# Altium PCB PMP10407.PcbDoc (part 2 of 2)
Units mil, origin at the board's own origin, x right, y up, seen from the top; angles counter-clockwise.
Board outline 4400 x 1900 mil, 4 copper layers (Top Layer, Signal Layer 1, Signal Layer 2, Bottom Layer), stack 60.6 mil thick; 66 components, 38 nets, 182 pads, 41 vias.
Unrouted connection lines stored in the file: 1.
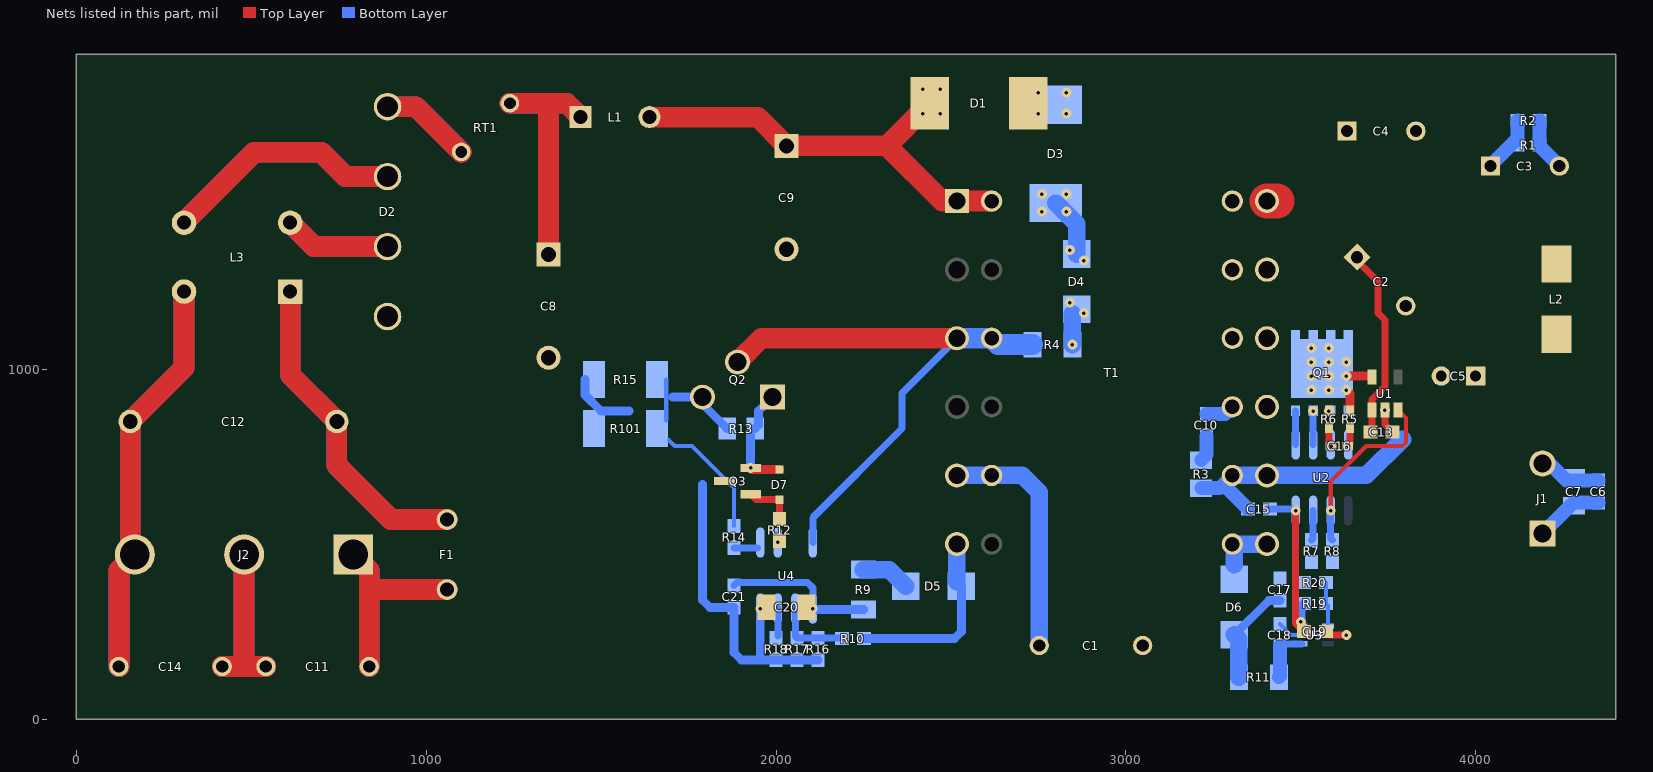
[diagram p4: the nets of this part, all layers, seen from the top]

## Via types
v1: diameter 28, hole 10, Top Layer to Bottom Layer, 41 vias

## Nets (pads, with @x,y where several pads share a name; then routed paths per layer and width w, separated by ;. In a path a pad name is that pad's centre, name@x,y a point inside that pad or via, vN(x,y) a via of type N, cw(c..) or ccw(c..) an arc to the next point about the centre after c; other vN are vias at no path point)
5VDD: C15.1 C19.1 R19.1 U2.4 U3.5 | length 480.4
  Top Layer w20: v1@3485,589.01 3485,273.51 C19.1@3508.51,250
  Bottom Layer w20: C15.1@3411.5,600 3480.51,600 v1(3485,595.51)
  Bottom Layer w25: v1(3500,277.26) 3500,321.49 R19.1@3508.51,330
EN: R8.2 U1.3 U2.2 | length 532.4
  Top Layer w12: v1(3585,595.51) 3585,678.54 3686.46,780 3790,780 3800,790 3800,860.16 U1.3@3777.4,882.76
  Bottom Layer w20: v1(3585,595.51) 3585,516.5 R8.2@3590,511.5
GND: C1.2 C8.2 C9.2 C20.2 C21.2 D2.4 Q3.3 R15.1 R16.1 R17.1 R18.1 R101.1 T1.5 T1.8 U4.4 | length 1829
  Bottom Layer w25: R15.1@1453.86,970 1453.86,926.14 1500,880 1580,880 ; 1790,670 1790,340 1811.5,318.5 C21.2@1880,318.5 1880,190 1901.5,168.5 R18.1@2000,168.5 R17.1@2060,168.5 R16.1@2120,168.5 ; 1955,175 v1(1955,315.51)
  Bottom Layer w50: T1.5@2517,696 T1.8@2616,696 2704,696 2752.36,647.64 C1.2@2752.36,210
GND2: C1.1 C2.2 C3.2 C4.2 C5.2 C6.2 C7.2 C11.2 C13.2 C14.1 C15.2 C17.2 C18.2 C19.2 J1.2 J2.2 Q1.1 Q1.2 Q1.3 R1.1 R2.1 R3.2 R6.2 R7.1 R8.1 R20.1 T1.17 T1.20 U1.2 U2.6 U3.2 | length 2369.5
  Top Layer w20: C19.2@3571.5,250 3581.5,240 v1(3630,240) ; v1(3740,882.76) 3740,841.5 C13.2@3761.5,820
  Top Layer w59.06: C14.1@417.64,150 480,150 ; J2.2@480,470 480,150 ; C11.2@542.36,150 480,150
  Bottom Layer w12: C18.2@3440,271.49 3471.5,240 U3.2@3577.41,240 v1(3630,240)
  Bottom Layer w20: Q1.3@3534.84,880.7 3534.84,784.65 U2.6@3535,784.49
  Bottom Layer w39.37: R3.2@3215,660 3268,660 T1.17@3304,696 ; 3288.5,660 C15.2@3348.5,600 ; R2.1@4181.5,1710 R1.1@4181.5,1640 4181.5,1636.93 C3.2@4238.43,1580 ; J1.2@4200,740 4258.5,681.5 C6.2@4350,681.5
  Bottom Layer w50: T1.17@3304,696 T1.20@3403,696 3686.79,696 3790.79,800
  Bottom Layer w59.06: C14.1@417.64,150 480,150 ; J2.2@480,470 480,150 ; C11.2@542.36,150 480,150
  other v1: 3534.84,880 3580,880
NetC2_1: C2.1 C3.1 C4.1 C13.1 L2.1 R1.2 R2.2 T1.13 T1.14 T1.23 T1.24 U1.1 | length 700.9
  Top Layer w20: 3680,1290 3720,1250 3720,1160 3740,1140 3740,950.16 3702.6,912.76 U1.1@3702.6,882.76 3702.6,824.09 C13.1@3698.5,820
  Top Layer w100: T1.24@3403,1480 T1.24@3431.57,1480
  Bottom Layer w39.37: C3.1@4041.57,1581.57 4118.5,1658.5 R2.2@4118.5,1710
NetC5_1: C5.1 C6.1 C7.1 J1.1 L2.2 | length 182.5
  Bottom Layer w39.37: J1.1@4200,540 4278.5,618.5 C6.1@4350,618.5
NetC8_1: C8.1 L1.1 RT1.1 | length 1290.7
  Top Layer w59.06: RT1.1@1239.6,1759.6 1401.98,1759.6 L1.1@1441.57,1720 ; C8.1@1350,1327.64 1350,1749.6
  Bottom Layer w59.06: RT1.1@1239.6,1759.6 1350,1759.6 ; C8.1@1350,1327.64 1350,1759.6 ; L1.1@1441.57,1720 1401.98,1759.6 1350,1759.6
NetC9_1: C9.1 D1.2 L1.2 T1.1 T1.12 | length 1250
  Top Layer w59.06: L1.2@1638.43,1720 1947.64,1720 C9.1@2030,1637.64 2317.15,1637.64 ; D1.2@2439.51,1760 2317.15,1637.64 ; T1.12@2616,1480 T1.1@2517,1480 2474.78,1480 2317.15,1637.64
  other v1: 2420,1730 2470,1730 2420,1800 2470,1800
NetC10_1: C10.1 R3.1 | length 74.7
  Bottom Layer w39.37: R3.1@3215,740 3230,755 C10.1@3230,808.5
NetC10_2: C10.2 Q1.5 Q1.6 Q1.7 Q1.8 Q1.9 R5.2 T1.15 T1.16 T1.21 T1.22 U1.5 | length 220.6
  Top Layer w25: v1(3630,940) 3640,930 R5.2@3640,879.76 ; v1(3630,980) 3699.84,980 U1.5@3702.6,977.24
  Bottom Layer w39.37: C10.2@3230,871.5 3283.5,871.5 T1.16@3304,892
  other v1: 3530,940 3580,940 3530,980 3580,980 3530,1020 3580,1020 3630,1020 3530,1060 3580,1060
NetC11_1: C11.1 F1.2 J2.1 | length 1126.7
  Top Layer w59.06: J2.1@792,470 837.64,424.36 837.64,370 ; C11.1@837.64,150 837.64,370 ; F1.2@1060,370 837.64,370
  Bottom Layer w59.06: J2.1@792,470 837.64,424.36 837.64,380 ; C11.1@837.64,150 837.64,380 ; F1.2@1060,370 847.64,370 837.64,380
NetC12_1: C12.1 F1.1 L3.1 | length 1862.1
  Top Layer w59.06: L3.1@611.57,1221.57 611.57,983.7 C12.1@745.28,850 745.28,724.72 900,570 F1.1@1060,570
  Bottom Layer w59.06: L3.1@611.57,1221.57 611.57,983.7 C12.1@745.28,850 745.28,724.72 900,570 F1.1@1060,570
NetC12_2: C12.2 C14.2 J2.3 L3.4 | length 2281.7
  Top Layer w59.06: C14.2@122.36,150 122.36,424.36 J2.3@168,470 ; J2.3@154.72,483.28 C12.2@154.72,850 308.43,1003.7 L3.4@308.43,1221.57
  Bottom Layer w59.06: C14.2@122.36,150 122.36,424.36 J2.3@168,470 ; J2.3@154.72,483.28 C12.2@154.72,850 308.43,1003.7 L3.4@308.43,1221.57
NetC16_1: C16.1 R5.1 U2.8 | length 55.2
  Top Layer w20: v1(3633.62,780) 3640,786.38 R5.1@3640,832.52
NetC16_2: C16.2 R6.1 U2.7 | length 55.2
  Top Layer w20: R6.1@3580,832.52 3580,786.38 v1(3586.38,780)
NetC17_1: C17.1 D6.1 R11.1 | length 296.9
  Bottom Layer w25: D6.1@3310,241.26 3311.26,241.26 3408.5,338.5 C17.1@3440,338.5
  Bottom Layer w50: D6.1@3310,241.26 3322.91,228.35 R11.1@3322.91,120
NetC18_1: C18.1 R11.2 U3.4 | length 154.8
  Bottom Layer w20: C18.1@3440,208.5 3445.91,214.41 U3.4@3502.6,214.41
  Bottom Layer w39.37: R11.2@3437.09,120 3440,122.92 C18.1@3440,208.5
NetC20_1: C20.1 C21.1 R9.1 U4.1 | length 436.6
  Bottom Layer w20: C21.1@1880,381.5 1888.5,390 2090,390 2105,375 v1(2105,315.51)
  Bottom Layer w25: U4.1@2107.6,312.91 R9.1@2250,312.91
NetD1_1: D1.1 D3.2
  other v1: 2750,1730 2830,1730 2750,1790 2830,1790
NetD2_1: D2.1 RT1.2 | length 528.2
  Top Layer w59.06: D2.1@890,1750 970.81,1750 RT1.2@1100.4,1620.4
  Bottom Layer w59.06: D2.1@890,1750 970.81,1750 RT1.2@1100.4,1620.4
NetD2_2: D2.2 L3.3 | length 1388.1
  Top Layer w59.06: L3.3@308.43,1418.43 510,1620 700,1620 770,1550 D2.2@890,1550
  Bottom Layer w59.06: L3.3@308.43,1418.43 510,1620 700,1620 770,1550 D2.2@890,1550
NetD2_3: D2.3 L3.2 | length 613.5
  Top Layer w59.06: L3.2@611.57,1418.43 680,1350 D2.3@890,1350
  Bottom Layer w59.06: L3.2@611.57,1418.43 680,1350 D2.3@890,1350
NetD3_1: D3.1 D4.1 | length 170.6
  Bottom Layer w50: D3.1@2800,1474.51 2860,1414.51 D4.1@2860,1328.74
  other v1: 2880,1310 2840,1340 2760,1450 2830,1450 2760,1500 2830,1500
NetD4_2: D4.2 R4.1 | length 88.3
  Bottom Layer w50: v1(2847.09,1070) D4.2@2847.09,1158.35
  other v1: 2880,1160 2840,1190
NetD5_1: D5.1 R9.2 | length 140.8
  Bottom Layer w50: R9.2@2250,427.09 2324.17,427.09 D5.1@2371.26,380
NetD5_2: D5.2 R10.2 T1.6 | length 525.6
  Bottom Layer w25: R10.2@2251.5,230 2510,230 2530,250 2530,378.74 D5.2@2528.74,380
  Bottom Layer w50: D5.2@2517,391.74 T1.6@2517,500
NetD6_2: D6.2 T1.18 T1.19 | length 160.4
  Bottom Layer w50: 3310,441.11 3310,494 T1.18@3304,500 T1.19@3403,500
NetD7_1: D7.1 Q2.1 Q3.2 R13.2 | length 295
  Top Layer w25: v1(1927.4,717.4) 1931.5,713.31 D7.1@2010,713.31
  Bottom Layer w25: v1(1927.4,717.4) R13.2@1927.4,817.4 ; R13.2@1940,830 1950,840 1950,880 Q2.1@1990,920
NetD7_2: D7.2 Q3.1 R12.1 | length 144.4
  Top Layer w20: Q3.1@1927.4,642.6 1943.31,626.69 D7.2@2010,626.69 R12.1@2010,571.5
NetQ1_4: Q1.4 U2.5 | length 96.4
  Bottom Layer w20: Q1.4@3484.51,880.7 3485,880.2 U2.5@3485,784.49
NetQ2_2: Q2.2 R4.2 T1.3 T1.10 U4.8 | length 1632.7
  Top Layer w59.06: Q2.2@1890,1020 1958,1088 T1.3@2517,1088
  Bottom Layer w20: U4.8@2105,504.49 2105,575 2360,830 2360,931 T1.3@2517,1088
  Bottom Layer w59.06: T1.3@2517,1088 T1.10@2616,1088 2634,1070 R4.2@2732.91,1070
NetQ2_3: Q2.3 R13.1 R14.2 R15.2 R101.2 | length 671
  Bottom Layer w12: R101.2@1686.14,853.86 R15.2@1686.14,970 ; 1694.17,796.38 1710.55,780 1760,780 1880,660 R14.2@1880,551.5
  Bottom Layer w25: 1704.93,920 Q2.3@1790,920 1790,900 R13.1@1860,830
NetR7_2: R7.2 U2.3 | length 86.1
  Bottom Layer w20: R7.2@3530,511.5 3535,516.5 U2.3@3535,595.51
NetR10_1: R10.1 R16.2 R17.2 U4.2 | length 213.1
  Bottom Layer w20: U4.2@2055,315.51 2055,236.5 R17.2@2060,231.5 R16.2@2120,231.5 R10.1@2187.01,231.5
NetR12_2: R12.2 U4.6
  other v1: 2005,504.49
NetR14_1: R14.1 U4.5 | length 66.9
  Bottom Layer w20: R14.1@1880,488.5 U4.5@1946.93,488.5
NetR18_2: R18.2 U4.3 | length 79
  Bottom Layer w20: R18.2@2005,236.5 U4.3@2005,315.51
NetR19_2: R19.2 R20.2 U3.1 | length 126.9
  Bottom Layer w12: R20.2@3571.5,390 R19.2@3571.5,330 3577.41,324.09 U3.1@3577.41,265.59
pads on no net: HS1.0 T1.2 T1.4 T1.7 T1.9 T1.11 U1.4 U2.1 U3.3

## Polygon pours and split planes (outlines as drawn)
NetD4_2 on Top Layer "D4_2" (solid, pour order 74): 2840,1010 2820,1030 2820,1060 2820,1210 2830,1220 2860,1220 2970,1220 2990,1200 2990,1030 2970,1010
NetC5_1 on Top Layer "C5_1" (solid, remove dead copper, pour order 75): 3970,1020 4130,1180 4180,1180 4380,1180 4390,1170 4390,980 4390,460 4380,450 4320,450 3980,450 3970,460
GND2 on Top Layer "GND2" (solid, remove dead copper, pour order 81): 3270,1880 3280,1890 3310,1890 4380,1890 4390,1880 4390,1870 4390,40 4370,20 3040,20 3020,40 3020,80 3020,490 3270,740
NetD3_1 on Top Layer "D3_1" (solid, pour order 73): 2740,1550 2720,1530 2720,1510 2720,1310 2720,1300 2740,1280 2760,1280 2970,1280 2990,1300 2990,1340 2990,1530 2970,1550
NetC10_2 on Top Layer "C10_2" (solid, remove dead copper, pour order 57): 3270,1200 3278.5,1208.5 3450,1208.5 3661.5,1208.5 3670,1200 3670,1180 3670,931.57 3658.43,920 3580,920 3460,920 3440,900 3440,870 3440,860 3430,850 3280,850 3270,860
NetC2_1 on Top Layer "NetC2_1" (solid, remove dead copper, pour order 53): 3270,1520 3270,1260 3280,1250 3290,1250 3640,1250 3710,1320 4080,1320 4090,1320 4170,1240 4250,1240 4280,1240 4290,1250 4290,1270 4290,1350 4100,1540 4100,1600 4090,1610 4040,1610 3770,1610 3670,1710 3620,1710 3590,1710 3410,1530 3280,1530
GND on Top Layer "GND" (solid, pour order 80): 850,1170 870,1190 900,1190 980,1190 1630,1190 1850,1410 2100,1410 2170,1340 2270,1240 2270,890 2400,760 2401.5,761.5 2490,761.5 2758.5,761.5 2780,740 2780,730 2780,40 2760,20 2740,20 1460,20 1440,40 1440,110 1440,570 1190,820 920,1090 870,1090 850,1110
NetD1_1 on Top Layer "D1_1" (solid, pour order 69): 2680,1660 2660,1680 2660,1720 2660,1870 2660.08,1870 2680,1889.92 2680.08,1890 2700,1890 2940,1890 2960,1870 2960,1720 2960,1680 2940,1660
NetC9_1 on Top Layer "C9_1" (solid, pour order 65): 1600,1870 1620,1890 1650,1890 1940,1890 2500,1890 2520,1870 2520,1830 2520,1580 2580,1520 2630,1520 2650,1500 2650,1470 2650,1460 2630,1440 2600,1440 2510,1440 2460,1440 2280,1440 2130,1590 2070,1590 1620,1590 1600,1610
NetC8_1 on Top Layer "C8_1" (solid, pour order 61): 1210,1870 1230,1890 1470,1890 1490,1870 1490,1840 1490,1310 1470,1290 1310,1290 1230,1290 1210,1310
NetD2_1 on Top Layer "D2_1" (solid, pour order 59): 850,1710 830,1730 830,1868.98 850,1888.98 851.02,1890 940,1890 1110,1890 1130,1870 1130,1840 1130,1610 1110,1590 1080,1590 1030,1640 960,1710
GND2 on Bottom Layer "GND2" (solid, remove dead copper, pour order 81): 3270,1880 3280,1890 3310,1890 4380,1890 4390,1880 4390,1870 4390,40 4370,20 3040,20 3020,40 3020,80 3020,490 3270,740
NetC10_2 on Bottom Layer "C10_2" (solid, remove dead copper, pour order 56): 3270,1200 3278.5,1208.5 3450,1208.5 3661.5,1208.5 3670,1200 3670,1180 3670,931.57 3658.43,920 3580,920 3460,920 3440,900 3440,870 3440,860 3430,850 3280,850 3270,860
NetQ2_3 on Bottom Layer "Q2_3" (solid, pour order 76): 1666.97,1030 1730,1030 1880,880 1880,815.93 1864.07,800 1786.97,800 1666.97,800 1657.38,809.59 1657.38,1020.41
GND on Bottom Layer "GND" (solid, pour order 77): 850,1170 870,1190 900,1190 980,1190 1630,1190 1850,1410 2100,1410 2170,1340 2270,1240 2270,890 2400,760 2401.5,761.5 2490,761.5 2758.5,761.5 2780,740 2780,730 2780,40 2760,20 2740,20 1460,20 1440,40 1440,110 1440,570 1190,820 920,1090 870,1090 850,1110
NetD3_1 on Bottom Layer "D3_1" (solid, pour order 72): 2740,1550 2720,1530 2720,1510 2720,1310 2720,1300 2740,1280 2760,1280 2970,1280 2990,1300 2990,1340 2990,1530 2970,1550
NetD1_1 on Bottom Layer "D1_1" (solid, pour order 66): 2680,1660 2660,1680 2660,1720 2660,1870 2660.08,1870 2680,1889.92 2680.08,1890 2700,1890 2940,1890 2960,1870 2960,1720 2960,1680 2940,1660
NetC9_1 on Bottom Layer "C9_1" (solid, pour order 62): 1600,1870 1620,1890 1650,1890 1940,1890 2500,1890 2520,1870 2520,1830 2520,1580 2580,1520 2630,1520 2650,1500 2650,1470 2650,1460 2630,1440 2600,1440 2510,1440 2460,1440 2280,1440 2130,1590 2070,1590 1620,1590 1600,1610
NetC8_1 on Bottom Layer "C8_1" (solid, pour order 60): 1210,1870 1230,1890 1470,1890 1490,1870 1490,1840 1490,1310 1470,1290 1310,1290 1230,1290 1210,1310
NetD2_1 on Bottom Layer "D2_1" (solid, pour order 58): 850,1710 830,1730 830,1868.98 850,1888.98 851.02,1890 940,1890 1110,1890 1130,1870 1130,1840 1130,1610 1110,1590 1080,1590 1030,1640 960,1710
NetD4_2 on Bottom Layer "D4_2" (solid, pour order 74): 2840,1010 2820,1030 2820,1060 2820,1210 2830,1220 2860,1220 2970,1220 2990,1200 2990,1030 2970,1010
NetD4_2 on Signal Layer 1 "D4_2" (solid, pour order 74): 2840,1010 2820,1030 2820,1060 2820,1210 2830,1220 2860,1220 2970,1220 2990,1200 2990,1030 2970,1010
NetC8_1 on Signal Layer 1 "C8_1" (solid, pour order 61): 1210,1870 1230,1890 1470,1890 1490,1870 1490,1840 1490,1310 1470,1290 1310,1290 1230,1290 1210,1310
NetD2_1 on Signal Layer 1 "D2_1" (solid, pour order 59): 850,1710 830,1730 830,1868.98 850,1888.98 851.02,1890 940,1890 1110,1890 1130,1870 1130,1840 1130,1610 1110,1590 1080,1590 1030,1640 960,1710
GND2 on Signal Layer 1 "GND2" (solid, remove dead copper, pour order 81): 3270,1880 3280,1890 3310,1890 4380,1890 4390,1880 4390,1870 4390,40 4370,20 3040,20 3020,40 3020,80 3020,490 3270,740
GND on Signal Layer 1 "GND" (solid, pour order 79): 850,1170 870,1190 900,1190 980,1190 1630,1190 1850,1410 2100,1410 2170,1340 2270,1240 2270,890 2400,760 2401.5,761.5 2490,761.5 2758.5,761.5 2780,740 2780,730 2780,40 2760,20 2740,20 1460,20 1440,40 1440,110 1440,570 1190,820 920,1090 870,1090 850,1110
NetD3_1 on Signal Layer 1 "D3_1" (solid, pour order 71): 2740,1550 2720,1530 2720,1510 2720,1310 2720,1300 2740,1280 2760,1280 2970,1280 2990,1300 2990,1340 2990,1530 2970,1550
NetD1_1 on Signal Layer 1 "D1_1" (solid, pour order 68): 2680,1660 2660,1680 2660,1720 2660,1870 2660.08,1870 2680,1889.92 2680.08,1890 2700,1890 2940,1890 2960,1870 2960,1720 2960,1680 2940,1660
NetC9_1 on Signal Layer 1 "C9_1" (solid, pour order 64): 1600,1870 1620,1890 1650,1890 1940,1890 2500,1890 2520,1870 2520,1830 2520,1580 2580,1520 2630,1520 2650,1500 2650,1470 2650,1460 2630,1440 2600,1440 2510,1440 2460,1440 2280,1440 2130,1590 2070,1590 1620,1590 1600,1610
NetC10_2 on Signal Layer 1 "C10_2" (solid, remove dead copper, pour order 55): 3270,1200 3278.5,1208.5 3450,1208.5 3661.5,1208.5 3670,1200 3670,1180 3670,931.57 3658.43,920 3580,920 3460,920 3440,900 3440,870 3440,860 3430,850 3280,850 3270,860
NetD4_2 on Signal Layer 2 "D4_2" (solid, pour order 74): 2840,1010 2820,1030 2820,1060 2820,1210 2830,1220 2860,1220 2970,1220 2990,1200 2990,1030 2970,1010
NetC8_1 on Signal Layer 2 "C8_1" (solid, pour order 61): 1210,1870 1230,1890 1470,1890 1490,1870 1490,1840 1490,1310 1470,1290 1310,1290 1230,1290 1210,1310
NetD2_1 on Signal Layer 2 "D2_1" (solid, pour order 59): 850,1710 830,1730 830,1868.98 850,1888.98 851.02,1890 940,1890 1110,1890 1130,1870 1130,1840 1130,1610 1110,1590 1080,1590 1030,1640 960,1710
GND2 on Signal Layer 2 "GND2" (solid, remove dead copper, pour order 81): 3270,1880 3280,1890 3310,1890 4380,1890 4390,1880 4390,1870 4390,40 4370,20 3040,20 3020,40 3020,80 3020,490 3270,740
GND on Signal Layer 2 "GND" (solid, pour order 78): 850,1170 870,1190 900,1190 980,1190 1630,1190 1850,1410 2100,1410 2170,1340 2270,1240 2270,890 2400,760 2401.5,761.5 2490,761.5 2758.5,761.5 2780,740 2780,730 2780,40 2760,20 2740,20 1460,20 1440,40 1440,110 1440,570 1190,820 920,1090 870,1090 850,1110
NetD3_1 on Signal Layer 2 "D3_1" (solid, pour order 70): 2740,1550 2720,1530 2720,1510 2720,1310 2720,1300 2740,1280 2760,1280 2970,1280 2990,1300 2990,1340 2990,1530 2970,1550
NetD1_1 on Signal Layer 2 "D1_1" (solid, pour order 67): 2680,1660 2660,1680 2660,1720 2660,1870 2660.08,1870 2680,1889.92 2680.08,1890 2700,1890 2940,1890 2960,1870 2960,1720 2960,1680 2940,1660
NetC9_1 on Signal Layer 2 "C9_1" (solid, pour order 63): 1600,1870 1620,1890 1650,1890 1940,1890 2500,1890 2520,1870 2520,1830 2520,1580 2580,1520 2630,1520 2650,1500 2650,1470 2650,1460 2630,1440 2600,1440 2510,1440 2460,1440 2280,1440 2130,1590 2070,1590 1620,1590 1600,1610
NetC10_2 on Signal Layer 2 "C10_2" (solid, remove dead copper, pour order 54): 3270,1200 3278.5,1208.5 3450,1208.5 3661.5,1208.5 3670,1200 3670,1180 3670,931.57 3658.43,920 3580,920 3460,920 3440,900 3440,870 3440,860 3430,850 3280,850 3270,860

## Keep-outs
Keep-Out Layer:
  text ".Layer_Name" at 577,-858.49 h60

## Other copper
Top Layer:
  text ".Layer_Name" at 577,-858.49 h60
Bottom Layer:
  text ".Layer_Name" at 577,-858.49 h60

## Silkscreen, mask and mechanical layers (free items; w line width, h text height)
Top Overlay:
  lines w7: 3510,365 3510,650
  lines w10: 3610,740 3650,700 3650,660 ; 3610,480 3760,480 3770,490 3770,650 3760,660 3610,660 3610,480
  text ".PRJ_Number" at 3690,50 h60
  text ".PCB_Rev" at 4200,50.01 h60
  text ".Layer_Name" at 577,-858.49 h60
Bottom Overlay:
  lines w10: 3180,460 3370,460 3390,440 ; 3480,180 3520,180 3550,150 ; 3550,150 3550.01,150
  text "UL94V-0" at 1630,150 h60
  text "MADE IN U.S." at 1630,30 h60
  text ".Layer_Name" at 577,-858.49 h60
Top Paste:
  text ".Layer_Name" at 577,-858.49 h60
Bottom Paste:
  text ".Layer_Name" at 577,-858.49 h60
Top Solder:
  text ".Layer_Name" at 577,-858.49 h60
  text ".Layer_Name" at 577,-858.49 h60
Bottom Solder:
  text ".Layer_Name" at 577,-858.49 h60
Drill Guide:
  text ".Layer_Name" at 577,-858.49 h60
M1 Board Outline:
  the board outline again, w10
  text ".Layer_Name" at 577,-858.49 h60
M2 Board Dimensions:
  rectangle: 0,-285.5 125,-160.5
  rectangle: 125,-410.5 500,-285.5
  lines w7: 0,-285.5 1000,-285.5 ; 125,-410.5 125,-160.5 ; 250,-410.5 250,-160.5 ; 500,-410.5 500,-160.5 ; 750,-410.5 750,-160.5 ; 0,-410.5 1000,-410.5 1000,-160.5 0,-160.5 0,-410.5
  text ".Layer_Name" at 577,-858.49 h60
M3 3D STEP Top:
  text ".Layer_Name" at 577,-858.49 h60
M4 3D STEP Bottom:
  text ".Layer_Name" at 577,-858.49 h60
M5 Assembly Top:
  lines w10: -292,-930.17 6308,-930.17 ; -292,-726.83 6310,-726.83 ; -292,-523.5 -292,-1133.5 3713,-1133.5 6310,-1133.5 6310,-523.5 -291.5,-523.5 -291.5,-1133.5 1284,-1133.5 ; 2173,-1133.5 2173,-523.5 ; 3440,-726.83 3440,-523.5 ; 4280,-726.83 4280,-523.5 ; 4902,-1140 4902,-937.17
  text "COMPONENTS MARKED 'DNP' SHOULD NOT BE POPULATED." at 1153.5,-318.5 h60
  text "ASSEMBLY VARIANT:" at 1153,-434 h60
  text ".VariantName" at 2189,-434 h60
  text "PCB VIEWED FROM TOP SIDE" at -228.5,-655.67 h60
  text "BOARD #:" at 2248,-655.67 h60
  text ".PRJ_Number" at 2793.5,-655.67 h60
  text "REV:" at 3638,-655.67 h60
  text ".PCB_Rev" at 3929.5,-655.67 h60
  text "SVN REV:" at 4476,-655.67 h60
  text ".VersionControl_RevNumber" at 4982,-655.67 h60
  text "IGNORE ->" at -228.5,-858.49 h60
  text "PLOT NAME =" at -228.5,-1064.34 h60
  text ".plot_File_Name" at 577,-1064.34 h60
  text "GENERATED    :" at 2250,-1064.34 h60
  text ".Print_Date" at 3119.5,-1064.34 h60
  text ".Print_Time" at 3848.5,-1064.34 h60
  text "TEXAS INSTRUMENTS" at 5113,-1064.34 h60
M6 Assembly Bottom:
  lines w10: -292.5,-727.33 6309.5,-727.33 ; -290.5,-930.67 6309.5,-930.67 ; 1115.5,-1140.5 1115.5,-937.67 ; 1737.5,-727.33 1737.5,-524 ; 2577.5,-727.33 2577.5,-524 ; 3844.5,-1134 3844.5,-524 ; 4733.5,-1134 6309,-1134 6309,-524 -292.5,-524 -292.5,-1134 2304.5,-1134 6309.5,-1134 6309.5,-524
  text "COMPONENTS MARKED 'DNP' SHOULD NOT BE POPULATED." at 6102,-318 h60
  text ".VariantName" at 5058,-434 h60
  text "ASSEMBLY VARIANT:" at 6097,-434 h60
  text ".VersionControl_RevNumber" at 1035.5,-656.17 h60
  text "SVN REV:" at 1541.5,-656.17 h60
  text ".PCB_Rev" at 2088,-656.17 h60
  text "REV:" at 2379.5,-656.17 h60
  text ".PRJ_Number" at 3224,-656.17 h60
  text "BOARD #:" at 3769.5,-656.17 h60
  text "PCB VIEWED FROM BOTTOM SIDE" at 6246,-656.17 h60
  text "IGNORE ->" at 2547.85,-858.49 h60
  text "TEXAS INSTRUMENTS" at 904.5,-1064.84 h60
  text ".Print_Time" at 2169,-1064.84 h60
  text ".Print_Date" at 2898,-1064.84 h60
  text "GENERATED    :" at 3767.5,-1064.84 h60
  text ".plot_File_Name" at 5440.5,-1064.84 h60
  text "PLOT NAME =" at 6246,-1064.84 h60
M9 Title Sheet:
  drawing of 57 lines, arcs and shapes, not listed
  text "1" at 739.84,8036.5 h70
  text "2" at 3235.5,8036.5 h70
  text "3" at 5724.84,8036.5 h70
  text "4" at 8231.51,8036.5 h70
  text "5" at 10730.5,8036.5 h70
  text "6" at 13235.5,8036.5 h70
  text "A" at -416.5,6893.5 h70
  text "A" at 14383.5,6893.5 h70
  text "B" at -416.5,4513.5 h70
  text "B" at 14383.5,4513.5 h70
  text "C" at -416.5,2138.5 h70
  text "C" at 14383.5,2138.5 h70
  text "PROJECT TITLE:" at 11343.5,277.5 h45
  text ".PRJ_Title" at 11393.5,144.17 h70
  text "DESIGNED FOR:" at 11343.5,-23.5 h45
  text ".PRJ_Customer" at 11393.5,-163.5 h70
  text "D" at -416.5,-231.5 h70
  text "D" at 14383.5,-231.5 h70
  text "FILE NAME:" at 11343.5,-323.5 h45
  text ".PCB_File_Name_No_Path" at 11393.5,-443.5 h70
  text "Texas Instruments (TI) and/or its licensors do not warrant the accuracy or completeness of this specification" at 6374,-605.34 h45
  text "ENGINEER:" at 11343.5,-613.5 h45
  text "LAYOUT BY:" at 12848.5,-613.5 h45
  text "or any information contained therein. TI and/or its licensors do not warrant that this design will meet" at 6329.01,-718 h45
  text ".PRJ_Engineer" at 11393.5,-768.49 h70
  text ".PCB_Layout" at 12899,-768.49 h70
  text "the specifications, will be suitable for your application or fit for any particular purpose, or will operate in" at 6329.01,-830.67 h45
  text ".Layer_Name" at 577,-858.49 h60
  text "ALTIUM DESIGNER VERSION:" at 12848.5,-923.5 h45
  text "an implementation. TI and/or its licensors do not warrant that the design is production worthy. You should" at 6329.01,-943.33 h45
  text "completely validate and test your design implementation to confirm the system functionality for your application." at 6374,-1056 h45
  text ".print_Scale" at 11393.5,-1056.83 h70
  text ".Application_BuildNumber" at 12899,-1056.83 h70
  text "1" at 739.84,-1263.5 h70
  text "2" at 3235.5,-1263.5 h70
  text "3" at 5724.84,-1263.5 h70
  text "4" at 8231.51,-1263.5 h70
  text "5" at 10730.5,-1263.5 h70
  text "6" at 13235.5,-1263.5 h70
M10 Fab Notes:
  drawing of 592 lines, arcs and shapes, not listed
  text "Layer" at 6620,5934.25 h60
  text "Name" at 7029.91,5934.25 h60
  text "Material" at 7969.65,5934.25 h60
  text "Thickness" at 8829.42,5934.25 h60
  text "Constant" at 9479.26,5934.25 h60
  text "Board Layer Stack" at 10049.12,5934.25 h60
  text "DESIGN INFORMATION" at 12381.02,5910 h60
  text "1" at 6620,5814.25 h60
  text "Top Overlay" at 7029.91,5814.25 h60
  text "MIN. TRACK WIDTH:" at 11736.46,5730 h60
  text "10" at 12832.7,5730 h60
  text "MIL" at 12987.46,5730 h60
  text "2" at 6620,5694.25 h60
  text "Top Solder" at 7029.91,5694.25 h60
  text "Solder Resist" at 7969.65,5694.25 h60
  text "0.40mil" at 8829.42,5694.25 h60
  text "3.5" at 9479.26,5694.25 h60
  text "MIN. CLEARANCE:" at 11736.46,5598 h60
  text "0.2" at 12772.7,5598 h60
  text "mm" at 12987.46,5598 h60
  text "3" at 6620,5574.25 h60
  text "Top Layer" at 7029.91,5574.25 h60
  text "Copper" at 7969.65,5574.25 h60
  text "1.40mil" at 8829.42,5574.25 h60
  text "MIN. VIA PAD SIZE:" at 11736.46,5466 h60
  text "10" at 12802.71,5466 h60
  text "MIL" at 12987.46,5466 h60
  text "4" at 6620,5454.25 h60
  text "Dielectric1" at 7029.91,5454.25 h60
  text "FR-4" at 7969.65,5454.25 h60
  text "10.00mil" at 8829.42,5454.25 h60
  text "4.8" at 9479.26,5454.25 h60
  text "5" at 6620,5334.25 h60
  text "Signal Layer 1" at 7029.91,5334.25 h60
  text "Copper" at 7969.65,5334.25 h60
  text "1.40mil" at 8829.42,5334.25 h60
  text "0.05mm (2MIL)" at 12431.46,5324.29 h60
  text "MINIMUM ANNULAR RING" at 11407.23,5320 h60
  text "EXTERNAL" at 13139.46,5320 h60
  text "6" at 6620,5214.25 h60
  text "Dielectric 3" at 7029.91,5214.25 h60
  text "FR-4" at 7969.65,5214.25 h60
  text "35.00mil" at 8829.42,5214.25 h60
  text "4.2" at 9479.26,5214.25 h60
  text "PER" at 11607.23,5202 h60
  text "IPC-D-275 CLASS 2 LEVEL C" at 11827.23,5202 h60
  text "7" at 6620,5094.25 h60
  text "Signal Layer 2" at 7029.91,5094.25 h60
  text "Copper" at 7969.65,5094.25 h60
  text "1.40mil" at 8829.42,5094.25 h60
  text "MIL, HOLES" at 13315.46,5089.71 h60
  text "+/-" at 12923,5089 h60
  text "+/-" at 13777,5089 h60
  text "REGISTRATION TOLERANCES:" at 11407.23,5084 h60
  text "METAL" at 12607,5084 h60
  text "5" at 13183.2,5084 h60
  text "3" at 14016.2,5084 h60
  text "MIL" at 14132.46,5084 h60
  text "8" at 6620,4974.25 h60
  text "Dielectric 2" at 7029.91,4974.25 h60
  text "FR-4" at 7969.65,4974.25 h60
  text "10.00mil" at 8829.42,4974.25 h60
  text "4.2" at 9479.26,4974.25 h60
  text "MATERIAL:" at 11332.46,4874.54 h60
  text "9" at 6620,4854.25 h60
  text "Bottom Layer" at 7029.91,4854.25 h60
  text "Copper" at 7969.65,4854.25 h60
  text "1.40mil" at 8829.42,4854.25 h60
  text "10" at 6620,4734.25 h60
  text "Bottom Solder" at 7029.91,4734.25 h60
  text "Solder Resist" at 7969.65,4734.25 h60
  text "0.40mil" at 8829.42,4734.25 h60
  text "3.5" at 9479.26,4734.25 h60
  text "FR-4 High Tg" at 12318.9,4734.21 h60
  text "FR-408" at 11753.46,4725.64 h60
  text "X" at 12165.46,4725.64 h60
  text "OTHER" at 13241.46,4725.64 h60
  text "11" at 6620,4614.25 h60
  text "Bottom Overlay" at 7029.91,4614.25 h60
  text "62 MIL (1.6mm) +/-10%" at 12073.56,4562.92 h60
  text "THICKNESS:" at 11407.23,4558.64 h60
  text "X" at 11945.4,4558.64 h60
  text "OTHER" at 13358.46,4558.64 h60
  text "TOLERANCE:" at 11407.23,4400.64 h60
  text "X" at 12246.53,4400.64 h60
  text "ANSI IPC-6012 TYPE 3 CLASS 2" at 12433.48,4400.64 h60
  text "OTHER +/-" at 12433.46,4244.64 h60
  text "BOW & TWIST:" at 11407.23,4087.64 h60
  text "X" at 12246.53,4087.64 h60
  text "ANSI IPC-6012 TYPE 3 CLASS 2" at 12433.48,4087.64 h60
  text "OTHER +/-" at 12433.46,3929.13 h60
  text "DRILLING:" at 11332.46,3790.64 h60
  text "REFERENCE:" at 11407.23,3673.64 h60
  text "X" at 12055.46,3673.64 h60
  text "AS SHOWN" at 12242.46,3673.64 h60
  text "X" at 12956.46,3673.64 h60
  text "NC_DRILL FILES" at 13093.46,3673.64 h60
  text "PTH MIN COPPER THICKNESS:" at 11407.23,3515.64 h60
  text "X" at 12757.46,3515.64 h60
  text "1MIL" at 12894.46,3515.64 h60
  text "OTHER" at 13391.46,3515.64 h60
  text "BOARD FINISH:" at 11332.46,3356.64 h60
  text "SILKSCREEN:" at 11487.68,3238.64 h60
  text "X" at 12436.46,3238.64 h60
  text "TOP" at 12562.46,3238.64 h60
  text "X" at 12946.46,3238.64 h60
  text "BOTTOM" at 13073.46,3238.64 h60
  text "SILKSCREEN COLOR:" at 11487.68,3071.64 h60
  text "X" at 12435.42,3071.64 h60
  text "WHITE" at 12562.46,3071.64 h60
  text "OTHER" at 13073.46,3071.64 h60
  text "SOLDER RESIST COLOR:" at 11487.68,2901.64 h60
  text "X" at 12055.42,2742.44 h60
  text "GREEN" at 12182.46,2742.44 h60
  text "BLUE" at 12773.46,2742.44 h60
  text "OTHER" at 13311.46,2742.44 h60
  text "IMMERSION GOLD (ENIG)" at 12393.46,2553.92 h60
  text "ENEPIG" at 13731,2550.64 h60
  text "SURFACE FINISH:" at 11332.46,2549.64 h60
  text "IMM. TIN/SILVER OR EQUIV" at 11662,2392.64 h60
  text "OTHER" at 13093.46,2392.64 h60
  text "X" at 11500,2390 h60
  text "ARRAY/PANEL:" at 11332.46,2213.64 h60
  text "CUT AND TRIM PER MECH LAYER 1" at 12393.46,2209.35 h60
  text "N.C. ROUTE" at 12393.46,2057.64 h60
  text "X" at 13072.46,2057.64 h60
  text "V. SCORE" at 13259.46,2057.64 h60
  text "CERTIFICATION:" at 11332.46,1920.64 h60
  text "MATERIALS AND WORKMANSHIP FOR ALL PCBS" at 12057.46,1920.64 h60
  text "TO MEET OR EXCEED THE REQUIREMENTS OF:" at 12057.46,1822.64 h60
  text "X" at 11683.96,1686.13 h60
  text "ANSI IPC-A-600F CLASS ->" at 11822.96,1686.13 h60
  text "X" at 13462.02,1686.13 h60
  text "2" at 13580.96,1686.14 h60
  text "1" at 13265.96,1684.64 h60
  text "3" at 13934.96,1684.64 h60
  text "X" at 11686.02,1526.64 h60
  text "UL 94V-0" at 11822.96,1526.64 h60
  text "X" at 12498.02,1526.64 h60
  text "RoHS" at 12634.96,1526.64 h60
  text "OTHER" at 13279.36,1526.64 h60
  text "PER ORDER" at 13676.42,1526.64 h60
  text "ADDITIONAL REQUIREMENTS:" at 11332.46,1385.64 h60
  text "MICROSECTION:" at 11407.23,1270.64 h60
  text "YES" at 12312.96,1270.64 h60
  text "REQUIRED" at 13174.46,1114.49 h60
  text "BARE BOARD ELEC. TEST:" at 11407.23,1111.64 h60
  text "NONE" at 12712.96,1111.64 h60
  text "PER ORDER" at 13766.46,1111.64 h60
  text "X" at 12580,1110 h60
  text "MANUFACTURER'S UL:" at 11407.23,954.64 h60
  text "RAIL" at 12572.96,950.35 h60
  text "METAL" at 13064.77,950.35 h60
  text "X" at 13440,950 h60
  text "SILK" at 13576.46,950.35 h60
  text ".Layer_Name" at 577,-858.49 h60
M11 Gerber Information:
  lines w10: -292,-930.17 6308,-930.17 ; -292,-726.83 6310,-726.83 ; -292,-523.5 -292,-1133.5 3713,-1133.5 6310,-1133.5 6310,-523.5 -291.5,-523.5 -291.5,-1133.5 1284,-1133.5 ; 2173,-1133.5 2173,-523.5 ; 3440,-726.83 3440,-523.5 ; 4280,-726.83 4280,-523.5 ; 4902,-1140 4902,-937.17
  text "ALL ARTWORK VIEWED FROM TOP SIDE" at -228.5,-655.67 h60
  text "BOARD #:" at 2248,-655.67 h60
  text ".PRJ_Number" at 2793.5,-655.67 h60
  text "REV:" at 3638,-655.67 h60
  text ".PCB_Rev" at 3929.5,-655.67 h60
  text "SVN REV:" at 4476,-655.67 h60
  text ".VersionControl_RevNumber" at 4982,-655.67 h60
  text "LAYER NAME =" at -228.5,-858.49 h60
  text "PLOT NAME =" at -228.5,-1064.34 h60
  text ".plot_File_Name" at 577,-1064.34 h60
  text "GENERATED    :" at 2250,-1064.34 h60
  text ".Print_Date" at 3119.5,-1064.34 h60
  text ".Print_Time" at 3848.5,-1064.34 h60
  text "TEXAS INSTRUMENTS" at 5113,-1064.34 h60
M12 Stackup:
  text ".Layer_Name" at 577,-858.49 h60
M13 Component Bodies Top:
  text ".Layer_Name" at 577,-858.49 h60
M14 Component Bodies Bottom:
  text ".Layer_Name" at 577,-858.49 h60
M15 Courtyards Top:
  text ".Layer_Name" at 577,-858.49 h60
M16 Courtyards Bottom:
  text ".Layer_Name" at 577,-858.49 h60
Drill Drawing:
  text ".legend" at 5122.5,725.5 h60
  text "Drill Table" at 5147.5,540.5 h60
  text ".Layer_Name" at 577,-858.49 h60

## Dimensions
0,0 to 0,1900 on M2 Board Dimensions
0,0 to 4400,0 on M2 Board Dimensions
0,-410.5 to 1000,-410.5 on M2 Board Dimensions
